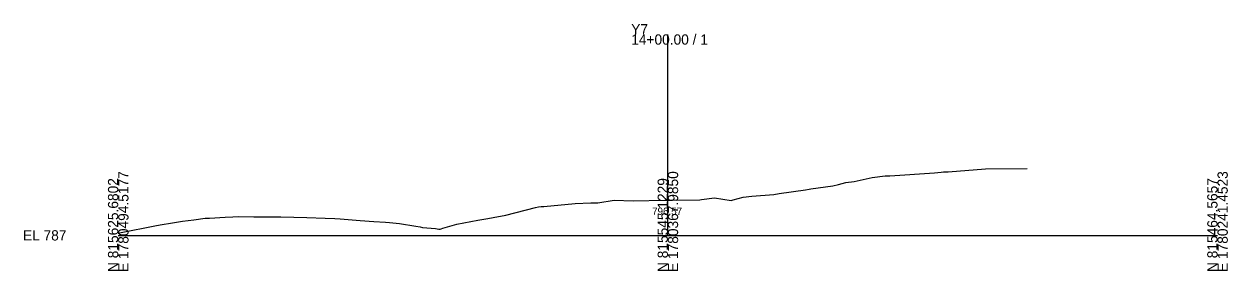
# Model space of a CAD drawing. Extents: x -26 to 2903, y -10 to 5536.
# Drawn here: x -25.7 to 302.8, y 3990.3 to 4057.6 of the extents above; entities that cross this region are included whole.
import ezdxf

# ---------------------------------------------------------------- set-up
doc = ezdxf.new("R2010")
doc.units = 0
for name, color, linetype in [('Exist Cross Section Cell', 7, 'Continuous'), ('Exist XS Center Line Elevation Label', 7, 'Continuous'), ('Exist XS Ground Line', 7, 'Continuous')]:
    doc.layers.add(name, color=color, linetype=linetype)

msp = doc.modelspace()

# ---------------------------------------------------------------- linework, layer by layer
at = {"layer": 'Exist Cross Section Cell'}
for p, q in [((150, 4000), (150, 4054.79)), ((0, 4000), (150, 4000)), ((150, 4000), (300, 4000))]:
    msp.add_line(p, q, dxfattribs=at)
at = {"layer": 'Exist XS Ground Line'}
for p, q in [((226.51, 4017.36), (236.7, 4018.09)), ((236.7, 4018.09), (248.06, 4018.26)), ((198.56, 4014.37), (200.8, 4014.68)), ((200.8, 4014.68), (205.73, 4015.81)), ((205.73, 4015.81), (209.33, 4016.2)), ((209.33, 4016.2), (210.61, 4016.27)), ((210.61, 4016.27), (222.72, 4017.07)), ((222.72, 4017.07), (224.6, 4017.25)), ((224.6, 4017.25), (225.22, 4017.33)), ((225.22, 4017.33), (226.51, 4017.36)), ((178.91, 4011.14), (180.33, 4011.42)), ((180.33, 4011.42), (187.55, 4012.42)), ((187.55, 4012.42), (188.57, 4012.57)), ((188.57, 4012.57), (189, 4012.66)), ((189, 4012.66), (195.02, 4013.54)), ((195.02, 4013.54), (196.55, 4013.85)), ((196.55, 4013.85), (198.56, 4014.37)), ((116.13, 4007.9), (124.72, 4008.72)), ((124.72, 4008.72), (128.97, 4008.82)), ((128.97, 4008.82), (130.85, 4008.86)), ((130.85, 4008.86), (135.32, 4009.56)), ((135.32, 4009.56), (140.52, 4009.44)), ((140.52, 4009.44), (149.15, 4009.56)), ((149.15, 4009.56), (149.96, 4009.57)), ((149.96, 4009.57), (150.71, 4009.58)), ((150.71, 4009.58), (158.68, 4009.72)), ((158.68, 4009.72), (159.2, 4009.75)), ((159.2, 4009.75), (162.75, 4010.22)), ((162.75, 4010.22), (167.26, 4009.53)), ((167.26, 4009.53), (167.8, 4009.69)), ((167.8, 4009.69), (170.53, 4010.43)), ((170.53, 4010.43), (172.94, 4010.68)), ((172.94, 4010.68), (178.91, 4011.14)), ((24.92, 4004.72), (29.21, 4004.96)), ((29.21, 4004.96), (31.25, 4005.04)), ((31.25, 4005.04), (32.75, 4005.1)), ((32.75, 4005.1), (37.05, 4005.08)), ((37.05, 4005.08), (44.37, 4005.01)), ((44.37, 4005.01), (51.51, 4004.83)), ((51.51, 4004.83), (56.48, 4004.71)), ((100.87, 4004.56), (102.31, 4004.87)), ((102.31, 4004.87), (105.82, 4005.49)), ((105.82, 4005.49), (113.88, 4007.57)), ((113.88, 4007.57), (114.73, 4007.77)), ((114.73, 4007.77), (115.46, 4007.85)), ((115.46, 4007.85), (116.13, 4007.9)), ((1.22, 4000.83), (9.57, 4002.48)), ((9.57, 4002.48), (9.95, 4002.62)), ((9.95, 4002.62), (11.49, 4002.89)), ((11.49, 4002.89), (14.81, 4003.42)), ((14.81, 4003.42), (17.5, 4003.87)), ((17.5, 4003.87), (20.65, 4004.23)), ((20.65, 4004.23), (23.75, 4004.64)), ((23.75, 4004.64), (24.92, 4004.72)), ((56.48, 4004.71), (59.1, 4004.57)), ((59.1, 4004.57), (60.54, 4004.49)), ((60.54, 4004.49), (66.04, 4004.09)), ((66.04, 4004.09), (69.73, 4003.82)), ((69.73, 4003.82), (72.96, 4003.62)), ((72.96, 4003.62), (74.06, 4003.53)), ((74.06, 4003.53), (76.73, 4003.22)), ((76.73, 4003.22), (81.18, 4002.5)), ((81.18, 4002.5), (82.38, 4002.3)), ((82.38, 4002.3), (83.05, 4002.17)), ((83.05, 4002.17), (86.57, 4001.83)), ((86.57, 4001.83), (87.08, 4001.77)), ((87.08, 4001.77), (87.45, 4001.73)), ((87.45, 4001.73), (87.85, 4001.7)), ((87.85, 4001.7), (88.16, 4001.79)), ((88.16, 4001.79), (88.59, 4001.93)), ((88.59, 4001.93), (92.38, 4003.08)), ((92.38, 4003.08), (98.15, 4004.1)), ((98.15, 4004.1), (100.87, 4004.56)), ((0, 4000.62), (1.22, 4000.83))]:
    msp.add_line(p, q, dxfattribs=at)

# ---------------------------------------------------------------- texts
at = {"layer": 'Exist Cross Section Cell'}
for s, p in [('Y7', (140, 4054.79)), ('14+00.00 / 1', (140, 4051.99)), ('EL 787', (-26, 3998.6))]:
    msp.add_text(s, height=2.8, dxfattribs=at).set_placement(p)
for s, p in [('N 815625.6802', (0, 3990)), ('E 1780494.5177', (2.8, 3990)), ('N 815545.1229', (150, 3990)), ('E 1780367.9850', (152.8, 3990)), ('N 815464.5657', (300, 3990)), ('E 1780241.4523', (302.8, 3990))]:
    msp.add_text(s, height=2.8, rotation=90, dxfattribs=at).set_placement(p)
at = {"layer": 'Exist XS Center Line Elevation Label'}
msp.add_text('796.57', height=2, dxfattribs=at).set_placement((145.7, 4005.57))

doc.saveas('drawing.dxf')
